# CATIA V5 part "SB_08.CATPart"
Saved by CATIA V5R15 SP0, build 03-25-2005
Part number: SB_08
Material "Bordeaux Red": density 7860 kg/m3, Young's modulus 2e+11 Pa, Poisson ratio 0.266
Bounding box of the stored display mesh (mm): x 0 to 79, y 0 to 632, z 0 to 49.2
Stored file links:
  E:\#01 CATIA Lecture Materials\#06 DMU\#11 DMU Page01 KIN EX11\SB_08.CATPart
  C:\Program Files\Dassault Systemes\B20\win_b64\startup\materials\Catalog.CATMaterial
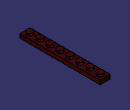
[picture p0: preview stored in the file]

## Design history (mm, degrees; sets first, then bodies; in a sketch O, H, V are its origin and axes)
Body1 (main body), material "Bordeaux Red"
  Sketch1 on xy-plane, origin (0, 0, 0), H (1, 0, 0), V (0, 1, 0)
    circle A1 centre (39.5, 39.5) radius 24
    point P1 (39.5, 39.5)
    radius A1 = 24
    distance P1 H = 39.5
    distance P1 V = 39.5
  Pad1: profile Sketch1, direction (0, 0, 1), length 49.2
  RectPattern1: of Pad1, direction 1 instances 8, spacing 79, along yz-plane
  Sketch2 on xy-plane, origin (0, 0, 0), H (1, 0, 0), V (0, 1, 0)
    point P1 (0, 632)
    line L1 (0, 632) -> (79, 632)
    line L2 (79, 632) -> (79, 0)
    line L3 (79, 0) -> (0, 0)
    line L4 (0, 0) -> (0, 632)
    point P3 (79, 0)
    distance L2 L4 = 79
    distance L1 L3 = 632 {= RectPattern1.Nb1 * 79mm}
    coincidence: P1 V, P3 H
    horizontal: L1 H, L3 H
    vertical: L2 V, L4 V
  Pad2: profile Sketch2, direction (0, 0, 1), length 32
  Shell1: ExtOffset 0, Face face of Pad2, IntOffset 15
